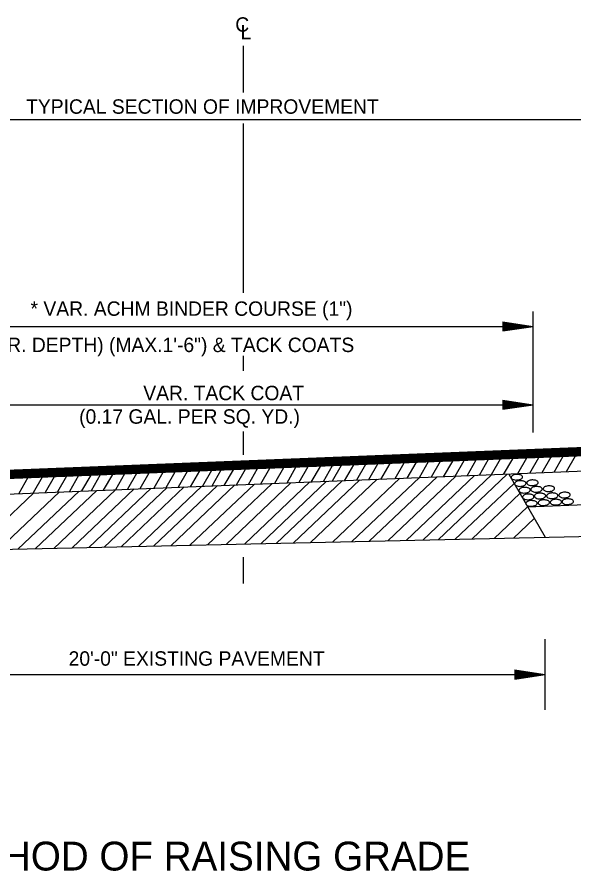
# Model space of a CAD drawing. Extents: x 3287 to 1767681, y -265 to 581440.
# Drawn here: x 3377.5 to 3423.9, y 32.8 to 103.8 of the extents above; entities that cross this region are included whole.
import ezdxf

# ---------------------------------------------------------------- set-up
doc = ezdxf.new("R2010")
doc.units = 0
doc.layers.add('R_Border PE', color=7, linetype='Continuous')

msp = doc.modelspace()

# ---------------------------------------------------------------- linework, layer by layer
at = {"layer": 'R_Border PE'}
for p, q in [((3396.368, 97.494), (3396.368, 101.392)), ((3332.286, 95.251), (3460.499, 95.251)), ((3396.368, 82.332), (3396.368, 94.923)), ((3396.368, 80.846), (3396.368, 82.332)), ((3420.474, 69.234), (3420.474, 79.285)), ((3417.96, 78.428), (3420.474, 78.046)), ((3417.96, 78.428), (3417.96, 77.669)), ((3417.96, 78.36), (3420.052, 78.046)), ((3417.96, 78.305), (3419.619, 78.046)), ((3417.96, 78.234), (3419.195, 78.046)), ((3417.96, 78.174), (3418.769, 78.046)), ((3372.107, 78.046), (3420.474, 78.046)), ((3417.96, 78.106), (3418.357, 78.046)), ((3417.96, 77.669), (3420.474, 78.046)), ((3417.96, 77.92), (3418.769, 78.046)), ((3417.96, 77.792), (3419.619, 78.046)), ((3417.96, 77.731), (3420.052, 78.046)), ((3417.96, 77.859), (3419.195, 78.046)), ((3417.96, 77.99), (3418.357, 78.046)), ((3396.368, 74.352), (3396.368, 75.613)), ((3417.96, 71.904), (3420.474, 71.529)), ((3417.96, 71.904), (3417.96, 71.15)), ((3417.96, 71.846), (3420.052, 71.529)), ((3417.96, 71.779), (3419.619, 71.529)), ((3417.96, 71.721), (3419.195, 71.529)), ((3372.107, 71.529), (3420.474, 71.529)), ((3417.96, 71.648), (3418.769, 71.529)), ((3417.96, 71.592), (3418.357, 71.529)), ((3417.96, 71.15), (3420.474, 71.529)), ((3417.96, 71.406), (3418.769, 71.529)), ((3417.96, 71.278), (3419.619, 71.529)), ((3417.96, 71.218), (3420.052, 71.529)), ((3417.96, 71.343), (3419.195, 71.529)), ((3417.96, 71.472), (3418.357, 71.529)), ((3331.631, 63.991), (3461.081, 69.155)), ((3331.799, 64.078), (3460.936, 69.227)), ((3331.966, 64.158), (3460.793, 69.3)), ((3332.136, 64.247), (3460.643, 69.373)), ((3332.286, 64.318), (3460.506, 69.441)), ((3396.368, 67.353), (3396.368, 69.298)), ((3351.342, 64.615), (3441.344, 68.199)), ((3351.396, 64.696), (3441.286, 68.284)), ((3351.19, 64.381), (3441.498, 67.974)), ((3351.245, 64.455), (3441.446, 68.051)), ((3351.294, 64.538), (3441.394, 68.127)), ((3411.732, 66.772), (3410.978, 65.455)), ((3412.743, 66.812), (3411.988, 65.495)), ((3413.754, 66.848), (3412.997, 65.541)), ((3414.701, 66.88), (3413.945, 65.571)), ((3415.715, 66.927), (3414.956, 65.605)), ((3416.724, 66.964), (3415.969, 65.649)), ((3417.734, 67.002), (3416.978, 65.691)), ((3418.739, 67.047), (3417.988, 65.732)), ((3419.916, 67.094), (3419.156, 65.775)), ((3420.921, 67.112), (3420.175, 65.821)), ((3421.942, 67.173), (3421.183, 65.858)), ((3422.951, 67.215), (3422.197, 65.9)), ((3423.959, 67.251), (3423.207, 65.94)), ((3350.365, 63.061), (3442.355, 66.722)), ((3393.711, 66.063), (3392.954, 64.748)), ((3394.491, 66.079), (3393.737, 64.766)), ((3395.505, 66.115), (3394.748, 64.808)), ((3396.513, 66.157), (3395.758, 64.842)), ((3397.523, 66.204), (3396.77, 64.884)), ((3398.535, 66.241), (3397.783, 64.929)), ((3399.706, 66.283), (3398.946, 64.97)), ((3400.711, 66.306), (3399.969, 65.012)), ((3401.729, 66.369), (3400.978, 65.052)), ((3402.743, 66.405), (3401.986, 65.099)), ((3403.752, 66.445), (3402.997, 65.133)), ((3404.496, 66.484), (3403.738, 65.165)), ((3405.512, 66.526), (3404.75, 65.206)), ((3406.515, 66.558), (3405.765, 65.254)), ((3407.526, 66.6), (3406.772, 65.287)), ((3408.537, 66.647), (3407.784, 65.326)), ((3409.712, 66.686), (3408.955, 65.376)), ((3410.715, 66.705), (3409.969, 65.418)), ((3378.444, 65.471), (3377.691, 64.156)), ((3379.616, 65.521), (3378.863, 64.205)), ((3380.624, 65.542), (3379.878, 64.247)), ((3381.64, 65.597), (3380.888, 64.284)), ((3382.654, 65.639), (3381.901, 64.326)), ((3383.661, 65.683), (3382.907, 64.371)), ((3384.448, 65.693), (3383.693, 64.384)), ((3385.469, 65.733), (3384.709, 64.416)), ((3386.472, 65.772), (3385.717, 64.46)), ((3387.485, 65.816), (3386.729, 64.502)), ((3388.493, 65.855), (3387.739, 64.541)), ((3389.661, 65.901), (3388.904, 64.583)), ((3390.665, 65.923), (3389.921, 64.63)), ((3391.692, 65.981), (3390.932, 64.674)), ((3392.7, 66.024), (3391.945, 64.706)), ((3401.952, 60.066), (3407.492, 65.334)), ((3403.786, 60.112), (3409.367, 65.415)), ((3405.383, 60.146), (3411.008, 65.473)), ((3406.832, 60.176), (3412.473, 65.539)), ((3408.382, 60.21), (3414.029, 65.596)), ((3409.909, 60.246), (3415.594, 65.659)), ((3411.287, 60.277), (3417.003, 65.714)), ((3412.557, 60.304), (3418.313, 65.764)), ((3418.434, 65.77), (3421.464, 60.507)), ((3384.787, 59.678), (3390.016, 64.641)), ((3386.197, 59.711), (3391.448, 64.695)), ((3387.637, 59.746), (3392.899, 64.755)), ((3388.899, 59.774), (3394.213, 64.81)), ((3390.322, 59.804), (3395.656, 64.858)), ((3391.916, 59.84), (3397.296, 64.931)), ((3393.367, 59.871), (3398.758, 64.989)), ((3394.923, 59.91), (3400.311, 65.047)), ((3396.452, 59.942), (3401.882, 65.115)), ((3397.83, 59.976), (3403.29, 65.165)), ((3399.101, 60), (3404.606, 65.22)), ((3400.514, 60.033), (3406.04, 65.277)), ((3413.966, 60.338), (3418.88, 64.995)), ((3373.925, 59.434), (3378.926, 64.196)), ((3376.006, 59.486), (3381.063, 64.279)), ((3377.602, 59.516), (3382.705, 64.349)), ((3379.045, 59.549), (3384.165, 64.402)), ((3380.603, 59.584), (3385.725, 64.467)), ((3382.13, 59.623), (3387.287, 64.536)), ((3383.509, 59.651), (3388.7, 64.583)), ((3415.409, 60.372), (3419.372, 64.14)), ((3420.003, 63.044), (3444.212, 64.009)), ((3417.234, 60.409), (3420.005, 63.042)), ((3418.849, 60.447), (3420.56, 62.077)), ((3361.044, 59.148), (3431.525, 60.733)), ((3396.368, 56.665), (3396.368, 58.861)), ((3421.464, 46.161), (3421.464, 52.047)), ((3371.133, 49.094), (3421.464, 49.094)), ((3418.949, 49.472), (3421.464, 49.094)), ((3418.949, 49.472), (3418.949, 48.718)), ((3418.949, 49.412), (3421.04, 49.094)), ((3418.949, 49.343), (3420.61, 49.094)), ((3418.949, 49.288), (3420.193, 49.094)), ((3418.949, 49.215), (3419.767, 49.094)), ((3418.949, 49.16), (3419.342, 49.094)), ((3418.949, 48.718), (3421.464, 49.094)), ((3418.949, 48.971), (3419.767, 49.094)), ((3418.949, 48.845), (3420.61, 49.094)), ((3418.949, 48.783), (3421.04, 49.094)), ((3418.949, 48.908), (3420.193, 49.094)), ((3418.949, 49.037), (3419.342, 49.094))]:
    msp.add_line(p, q, dxfattribs=at)
for points in [[(3419.11, 65.275), (3418.942, 65.278), (3418.759, 65.343), (3418.652, 65.433), (3418.641, 65.485), (3418.684, 65.597), (3418.748, 65.644), (3418.854, 65.697), (3419.018, 65.734), (3419.095, 65.742), (3419.223, 65.731), (3419.361, 65.71), (3419.467, 65.673), (3419.568, 65.587), (3419.585, 65.531), (3419.556, 65.437), (3419.48, 65.369), (3419.404, 65.322), (3419.289, 65.294), (3419.217, 65.278), (3419.11, 65.275)], [(3419.4, 64.747), (3419.232, 64.75), (3419.049, 64.815), (3418.943, 64.905), (3418.931, 64.957), (3418.975, 65.068), (3419.038, 65.115), (3419.145, 65.169), (3419.308, 65.206), (3419.386, 65.214), (3419.514, 65.203), (3419.651, 65.182), (3419.758, 65.145), (3419.858, 65.059), (3419.876, 65.002), (3419.847, 64.908), (3419.771, 64.84), (3419.695, 64.793), (3419.58, 64.766), (3419.507, 64.75), (3419.4, 64.747)], [(3419.757, 64.192), (3419.589, 64.195), (3419.406, 64.26), (3419.299, 64.35), (3419.288, 64.402), (3419.332, 64.514), (3419.395, 64.561), (3419.501, 64.614), (3419.665, 64.651), (3419.743, 64.659), (3419.87, 64.648), (3420.008, 64.627), (3420.115, 64.59), (3420.215, 64.504), (3420.233, 64.447), (3420.204, 64.354), (3420.128, 64.286), (3420.052, 64.239), (3419.937, 64.211), (3419.864, 64.195), (3419.757, 64.192)], [(3420.404, 64.813), (3420.236, 64.816), (3420.053, 64.881), (3419.947, 64.971), (3419.935, 65.023), (3419.979, 65.135), (3420.042, 65.181), (3420.149, 65.235), (3420.312, 65.272), (3420.39, 65.28), (3420.518, 65.269), (3420.655, 65.248), (3420.762, 65.211), (3420.862, 65.125), (3420.88, 65.068), (3420.851, 64.974), (3420.775, 64.906), (3420.699, 64.86), (3420.584, 64.832), (3420.511, 64.816), (3420.404, 64.813)], [(3420.748, 64.271), (3420.58, 64.274), (3420.397, 64.339), (3420.29, 64.43), (3420.279, 64.481), (3420.322, 64.593), (3420.385, 64.64), (3420.492, 64.693), (3420.656, 64.73), (3420.733, 64.739), (3420.861, 64.727), (3420.998, 64.706), (3421.105, 64.669), (3421.206, 64.583), (3421.223, 64.527), (3421.194, 64.433), (3421.118, 64.365), (3421.042, 64.318), (3420.927, 64.29), (3420.855, 64.274), (3420.748, 64.271)], [(3421.778, 64.324), (3421.61, 64.327), (3421.427, 64.392), (3421.32, 64.482), (3421.309, 64.534), (3421.353, 64.646), (3421.416, 64.693), (3421.522, 64.746), (3421.686, 64.783), (3421.763, 64.791), (3421.891, 64.78), (3422.029, 64.759), (3422.136, 64.722), (3422.236, 64.636), (3422.254, 64.579), (3422.225, 64.486), (3422.148, 64.418), (3422.072, 64.371), (3421.958, 64.343), (3421.885, 64.327), (3421.778, 64.324)], [(3420.061, 63.637), (3419.893, 63.64), (3419.71, 63.705), (3419.603, 63.796), (3419.592, 63.847), (3419.635, 63.959), (3419.699, 64.006), (3419.805, 64.059), (3419.969, 64.096), (3420.046, 64.105), (3420.174, 64.093), (3420.312, 64.072), (3420.418, 64.035), (3420.519, 63.949), (3420.536, 63.893), (3420.507, 63.799), (3420.431, 63.731), (3420.355, 63.684), (3420.24, 63.656), (3420.168, 63.64), (3420.061, 63.637)], [(3421.038, 63.716), (3420.87, 63.72), (3420.687, 63.784), (3420.581, 63.875), (3420.569, 63.927), (3420.613, 64.038), (3420.676, 64.085), (3420.783, 64.138), (3420.946, 64.176), (3421.024, 64.184), (3421.152, 64.172), (3421.289, 64.151), (3421.396, 64.114), (3421.496, 64.028), (3421.514, 63.972), (3421.485, 63.878), (3421.409, 63.81), (3421.333, 63.763), (3421.218, 63.736), (3421.145, 63.72), (3421.038, 63.716)], [(3422.055, 63.729), (3421.887, 63.733), (3421.704, 63.797), (3421.598, 63.888), (3421.586, 63.94), (3421.63, 64.051), (3421.693, 64.098), (3421.8, 64.152), (3421.963, 64.189), (3422.041, 64.197), (3422.169, 64.186), (3422.306, 64.165), (3422.413, 64.127), (3422.513, 64.042), (3422.531, 63.985), (3422.502, 63.891), (3422.426, 63.823), (3422.35, 63.776), (3422.235, 63.749), (3422.162, 63.733), (3422.055, 63.729)], [(3423.086, 63.796), (3422.917, 63.799), (3422.735, 63.863), (3422.628, 63.954), (3422.617, 64.006), (3422.66, 64.117), (3422.723, 64.164), (3422.83, 64.218), (3422.993, 64.255), (3423.071, 64.263), (3423.199, 64.252), (3423.336, 64.231), (3423.443, 64.193), (3423.544, 64.108), (3423.561, 64.051), (3423.532, 63.957), (3423.456, 63.889), (3423.38, 63.842), (3423.265, 63.815), (3423.192, 63.799), (3423.086, 63.796)], [(3420.325, 63.095), (3420.157, 63.099), (3419.974, 63.163), (3419.867, 63.254), (3419.856, 63.306), (3419.9, 63.417), (3419.963, 63.464), (3420.069, 63.518), (3420.233, 63.555), (3420.311, 63.563), (3420.438, 63.552), (3420.576, 63.531), (3420.683, 63.493), (3420.783, 63.408), (3420.801, 63.351), (3420.772, 63.257), (3420.696, 63.189), (3420.619, 63.142), (3420.505, 63.115), (3420.432, 63.099), (3420.325, 63.095)], [(3421.355, 63.162), (3421.187, 63.165), (3421.004, 63.229), (3420.898, 63.32), (3420.886, 63.372), (3420.93, 63.483), (3420.993, 63.53), (3421.1, 63.584), (3421.263, 63.621), (3421.341, 63.629), (3421.469, 63.618), (3421.606, 63.597), (3421.713, 63.559), (3421.813, 63.474), (3421.831, 63.417), (3421.802, 63.323), (3421.726, 63.255), (3421.65, 63.208), (3421.535, 63.181), (3421.462, 63.165), (3421.355, 63.162)], [(3422.359, 63.201), (3422.191, 63.204), (3422.008, 63.269), (3421.901, 63.36), (3421.89, 63.411), (3421.934, 63.523), (3421.997, 63.57), (3422.104, 63.623), (3422.267, 63.661), (3422.345, 63.669), (3422.472, 63.657), (3422.61, 63.636), (3422.717, 63.599), (3422.817, 63.513), (3422.835, 63.457), (3422.806, 63.363), (3422.73, 63.295), (3422.654, 63.248), (3422.539, 63.221), (3422.466, 63.204), (3422.359, 63.201)], [(3423.35, 63.241), (3423.182, 63.244), (3422.999, 63.309), (3422.892, 63.399), (3422.881, 63.451), (3422.924, 63.563), (3422.988, 63.61), (3423.094, 63.663), (3423.258, 63.7), (3423.335, 63.708), (3423.463, 63.697), (3423.601, 63.676), (3423.707, 63.639), (3423.808, 63.553), (3423.825, 63.496), (3423.796, 63.403), (3423.72, 63.335), (3423.644, 63.288), (3423.529, 63.26), (3423.457, 63.244), (3423.35, 63.241)]]:
    msp.add_spline(points, degree=3, dxfattribs=at)

# ---------------------------------------------------------------- texts
for s, height, p in [('C', 1.2, (3395.692, 102.554)), ('L', 1.2, (3396.121, 101.921)), ('TYPICAL SECTION OF IMPROVEMENT', 1.2, (3378.289, 95.731)), ('* VAR. ACHM BINDER COURSE (1")', 1.2, (3378.658, 78.926)), ('(VAR. DEPTH) (MAX.1\'-6") & TACK COATS', 1.2, (3374.041, 75.912)), ('VAR. TACK COAT', 1.2, (3388.037, 71.91)), ('(0.17 GAL. PER SQ. YD.)', 1.2, (3382.701, 69.953)), ('20\'-0" EXISTING PAVEMENT', 1.2, (3381.826, 49.827)), ('METHOD OF RAISING GRADE', 2.4, (3369.591, 32.796))]:
    msp.add_text(s, height=height, dxfattribs=at).set_placement(p)

doc.saveas('drawing.dxf')
